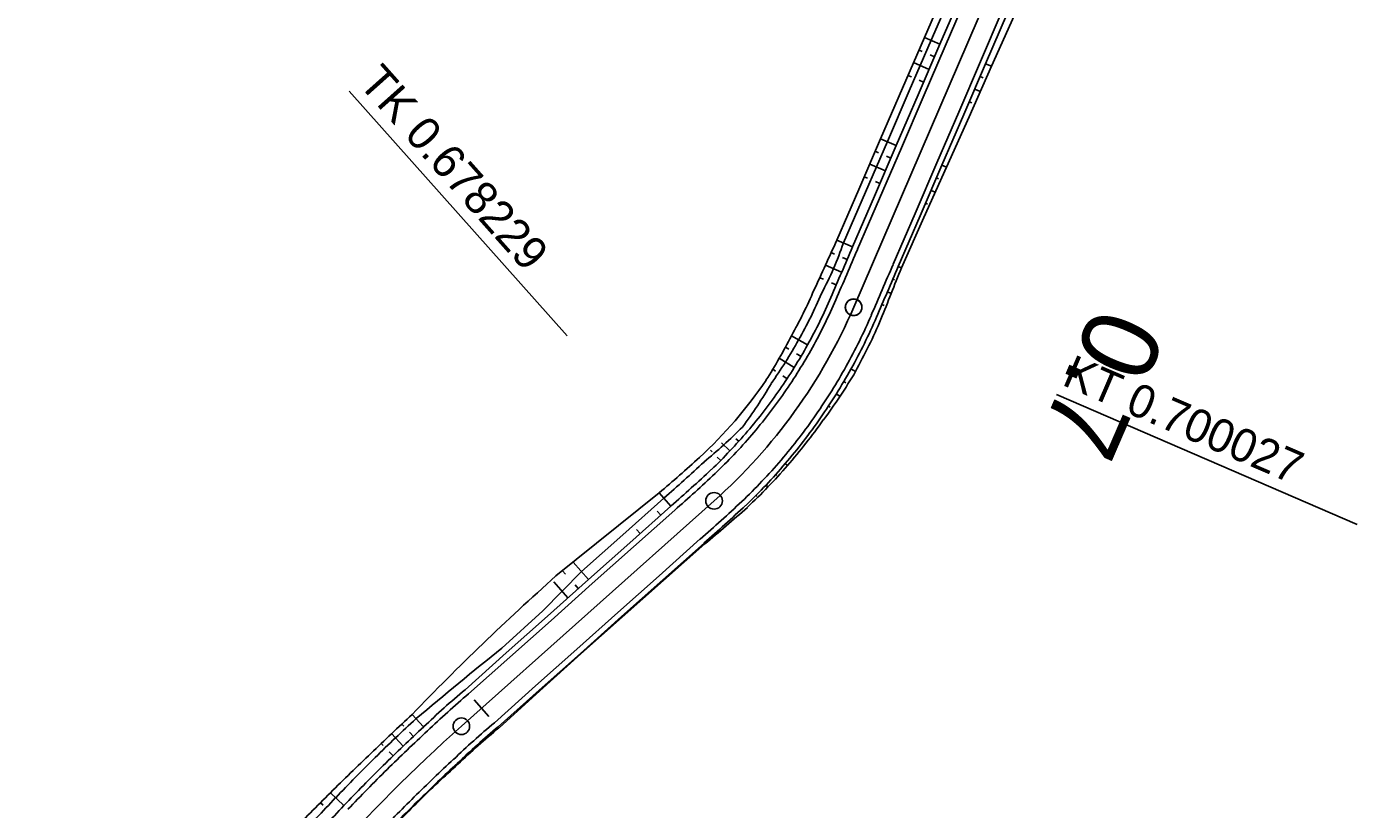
# Model space of a CAD drawing. Extents: x -481656 to -478728, y -1113199 to -1110710.
# Drawn here: x -480192.1 to -480071.5, y -1112507.2 to -1112436.3 of the extents above; entities that cross this region are included whole.
import ezdxf

# ---------------------------------------------------------------- set-up
doc = ezdxf.new("R2010")
doc.units = 0
for name, color, linetype in [('C14_HATCH_SLOPE_L', 7, 'Continuous'), ('C14_HATCH_SLOPE_R', 7, 'Continuous'), ('C14_HECTOMETRY', 7, 'Continuous'), ('C14_HLBODY', 7, 'Continuous'), ('C14_HRANA_TELESO', 7, 'Continuous'), ('C14_KORUNA', 7, 'Continuous'), ('C14_OSA', 7, 'Continuous'), ('C14_PRIKOP', 7, 'Continuous'), ('C14_STANICENI', 7, 'Continuous'), ('C14_VOZOVKA', 7, 'Continuous'), ('C14_ZPEVKRAJ', 7, 'Continuous')]:
    doc.layers.add(name, color=color, linetype=linetype)

msp = doc.modelspace()

# ---------------------------------------------------------------- linework, layer by layer
at = {"layer": 'C14_HATCH_SLOPE_L'}
for p, q in [((-480109.3, -1112437.88), (-480110.71, -1112437.27)), ((-480110.9, -1112438.55), (-480111.2, -1112438.42)), ((-480109.79, -1112439.02), (-480110.19, -1112438.85)), ((-480110.29, -1112440.17), (-480111.7, -1112439.56)), ((-480111.89, -1112440.84), (-480112.2, -1112440.71)), ((-480110.78, -1112441.32), (-480111.18, -1112441.15)), ((-480113.26, -1112447.06), (-480114.68, -1112446.45)), ((-480114.87, -1112447.72), (-480115.17, -1112447.59)), ((-480114.25, -1112449.35), (-480115.67, -1112448.74)), ((-480113.75, -1112448.21), (-480114.16, -1112448.03)), ((-480115.86, -1112450.02), (-480116.17, -1112449.89)), ((-480114.74, -1112450.5), (-480115.15, -1112450.32)), ((-480117.22, -1112456.24), (-480118.65, -1112455.63)), ((-480118.85, -1112456.9), (-480119.17, -1112456.76)), ((-480117.71, -1112457.39), (-480118.13, -1112457.21)), ((-480118.21, -1112458.54), (-480119.68, -1112457.9)), ((-480119.87, -1112459.18), (-480120.2, -1112459.04)), ((-480118.7, -1112459.69), (-480119.12, -1112459.51)), ((-480121.3, -1112465.11), (-480122.76, -1112464.3)), ((-480121.3, -1112465.11), (-480122.76, -1112464.3)), ((-480123, -1112465.5), (-480123.3, -1112465.32)), ((-480123, -1112465.5), (-480123.3, -1112465.32)), ((-480121.9, -1112466.15), (-480122.29, -1112465.92)), ((-480121.9, -1112466.15), (-480122.29, -1112465.92)), ((-480122.51, -1112467.17), (-480123.86, -1112466.33)), ((-480122.51, -1112467.17), (-480123.86, -1112466.33)), ((-480124.19, -1112467.5), (-480124.45, -1112467.33)), ((-480124.19, -1112467.5), (-480124.45, -1112467.33)), ((-480123.16, -1112468.18), (-480123.55, -1112467.92)), ((-480123.16, -1112468.18), (-480123.55, -1112467.92)), ((-480128.34, -1112474.72), (-480129.11, -1112473.99)), ((-480127.53, -1112473.84), (-480127.79, -1112473.61)), ((-480129.94, -1112474.81), (-480130.09, -1112474.66)), ((-480129.17, -1112475.58), (-480129.48, -1112475.27)), ((-480133.68, -1112479.71), (-480134.74, -1112478.51)), ((-480134.61, -1112480.54), (-480134.93, -1112480.18)), ((-480136.48, -1112482.2), (-480136.8, -1112481.84)), ((-480141.14, -1112486.36), (-480142.54, -1112484.79)), ((-480143.23, -1112485.89), (-480143.52, -1112485.57)), ((-480143.01, -1112488.02), (-480144.3, -1112486.58)), ((-480142.08, -1112487.19), (-480142.37, -1112486.86)), ((-480157.89, -1112499.64), (-480158.07, -1112499.45)), ((-480156.09, -1112499.71), (-480157.13, -1112498.58)), ((-480157.94, -1112501.45), (-480159.01, -1112500.32)), ((-480157.02, -1112500.57), (-480157.36, -1112500.2)), ((-480159.75, -1112501.4), (-480159.93, -1112501.21)), ((-480158.85, -1112502.32), (-480159.21, -1112501.96)), ((-480163.31, -1112506.83), (-480164.53, -1112505.68)), ((-480165.19, -1112506.81), (-480165.45, -1112506.58))]:
    msp.add_line(p, q, dxfattribs=at)
at = {"layer": 'C14_HATCH_SLOPE_R'}
for p, q in [((-480105.17, -1112439.66), (-480104.62, -1112439.89)), ((-480105.66, -1112440.8), (-480105.4, -1112440.92)), ((-480105.13, -1112441.03), (-480105.13, -1112441.03)), ((-480106.16, -1112441.95), (-480105.64, -1112442.17)), ((-480106.65, -1112443.1), (-480106.4, -1112443.21)), ((-480106.15, -1112443.31), (-480106.15, -1112443.31)), ((-480109.12, -1112448.84), (-480108.7, -1112449.02)), ((-480109.62, -1112449.99), (-480109.42, -1112450.07)), ((-480109.22, -1112450.16), (-480109.22, -1112450.16)), ((-480110.11, -1112451.14), (-480109.73, -1112451.3)), ((-480110.61, -1112452.28), (-480110.42, -1112452.36)), ((-480110.24, -1112452.44), (-480110.24, -1112452.44)), ((-480113.08, -1112458.02), (-480112.8, -1112458.15)), ((-480113.58, -1112459.17), (-480113.42, -1112459.24)), ((-480113.26, -1112459.31), (-480113.26, -1112459.31)), ((-480114.07, -1112460.32), (-480113.72, -1112460.47)), ((-480114.57, -1112461.47), (-480114.37, -1112461.55)), ((-480114.18, -1112461.63), (-480114.18, -1112461.63)), ((-480117.37, -1112467.3), (-480116.96, -1112467.53)), ((-480118.7, -1112469.55), (-480118.36, -1112469.76)), ((-480118.02, -1112468.44), (-480117.83, -1112468.54)), ((-480117.65, -1112468.66), (-480117.65, -1112468.66)), ((-480119.4, -1112470.65), (-480119.25, -1112470.75)), ((-480119.1, -1112470.85), (-480119.1, -1112470.85)), ((-480123.32, -1112475.87), (-480123.12, -1112476.04)), ((-480125.07, -1112477.81), (-480124.89, -1112477.98)), ((-480124.18, -1112476.85), (-480124.09, -1112476.94)), ((-480123.99, -1112477.02), (-480123.99, -1112477.02)), ((-480125.98, -1112478.75), (-480125.9, -1112478.83)), ((-480125.81, -1112478.91), (-480125.81, -1112478.91)), ((-480131.61, -1112483.9), (-480131.58, -1112483.93)), ((-480131.55, -1112483.97), (-480131.55, -1112483.97)), ((-480130.68, -1112483.07), (-480130.61, -1112483.14)), ((-480132.55, -1112484.73), (-480132.49, -1112484.79)), ((-480133.48, -1112485.56), (-480133.45, -1112485.59)), ((-480133.43, -1112485.62), (-480133.43, -1112485.62)), ((-480138.15, -1112489.72), (-480138.11, -1112489.77)), ((-480139.08, -1112490.55), (-480139.06, -1112490.57)), ((-480139.04, -1112490.59), (-480139.04, -1112490.59)), ((-480140.95, -1112492.22), (-480140.93, -1112492.23)), ((-480140.91, -1112492.25), (-480140.91, -1112492.25)), ((-480140.01, -1112491.38), (-480139.98, -1112491.42)), ((-480146.55, -1112497.21), (-480146.52, -1112497.24)), ((-480146.49, -1112497.27), (-480146.49, -1112497.27)), ((-480145.61, -1112496.37), (-480145.56, -1112496.43)), ((-480147.48, -1112498.04), (-480147.41, -1112498.11)), ((-480148.41, -1112498.87), (-480148.38, -1112498.91)), ((-480148.34, -1112498.95), (-480148.34, -1112498.95)), ((-480153.04, -1112503.02), (-480152.97, -1112503.08)), ((-480153.94, -1112503.86), (-480153.91, -1112503.89)), ((-480153.88, -1112503.92), (-480153.88, -1112503.92)), ((-480155.72, -1112505.55), (-480155.7, -1112505.58)), ((-480155.67, -1112505.6), (-480155.67, -1112505.6)), ((-480154.83, -1112504.7), (-480154.78, -1112504.76))]:
    msp.add_line(p, q, dxfattribs=at)
at = {"layer": 'C14_HECTOMETRY'}
msp.add_circle((-480117.13, -1112461.72), 0.75, dxfattribs=at)
at = {"layer": 'C14_HLBODY'}
for p, q in [((-480162.84, -1112442.14), (-480143.08, -1112464.31)), ((-480098.75, -1112469.61), (-480071.48, -1112481.37))]:
    msp.add_line(p, q, dxfattribs=at)
for centre in [(-480117.12, -1112461.7), (-480129.77, -1112479.24), (-480152.67, -1112499.65)]:
    msp.add_circle(centre, 0.75, dxfattribs=at)
at = {"layer": 'C14_HRANA_TELESO'}
for p, q in [((-480110.71, -1112437.27), (-480108.72, -1112432.68)), ((-480104.62, -1112439.89), (-480102.58, -1112435.33)), ((-480112.69, -1112441.86), (-480110.71, -1112437.27)), ((-480106.66, -1112444.46), (-480104.62, -1112439.89)), ((-480114.68, -1112446.45), (-480112.69, -1112441.86)), ((-480108.7, -1112449.02), (-480106.66, -1112444.46)), ((-480116.66, -1112451.04), (-480114.68, -1112446.45)), ((-480110.75, -1112453.58), (-480108.7, -1112449.02)), ((-480118.65, -1112455.63), (-480116.66, -1112451.04)), ((-480112.8, -1112458.15), (-480110.75, -1112453.58)), ((-480144.1, -1112486.04), (-480134.74, -1112478.51)), ((-480134.36, -1112486.45), (-480130.61, -1112483.14)), ((-480138.11, -1112489.77), (-480134.36, -1112486.45)), ((-480149, -1112492.58), (-480145.3, -1112489.21)), ((-480141.85, -1112493.08), (-480138.11, -1112489.77)), ((-480145.56, -1112496.43), (-480141.85, -1112493.08)), ((-480149.26, -1112499.79), (-480145.56, -1112496.43))]:
    msp.add_line(p, q, dxfattribs=at)
for centre, radius, start, end in [((-485943.29, -1109801.96), 6400.66, 335.461603, 335.50635), ((-473992.43, -1114890.71), 6586.07, 158.324428, 158.367956), ((-480163, -1112441.84), 46.08, 330.828, 336.5575), ((-480163.1, -1112442.04), 52.71, 331.0858, 336.8154), ((-480163.9, -1112443.35), 46.16, 327.2716, 333.005), ((-480158.18, -1112445.91), 39.98, 312.6689, 325.9265), ((-480162.22, -1112440.65), 52.65, 323.5666, 329.2985), ((-480162.71, -1112441.49), 52.54, 318.8842, 324.6141), ((-480224.17, -1112372.54), 138.66, 310.1615, 312.1723), ((-480162.75, -1112441.61), 52.5, 313.2855, 319.0153), ((-480231.26, -1112362.09), 157.43, 309.7394, 311.5913), ((-479986.79, -1112662.6), 236.47, 131.7, 136.0823), ((-480053.4, -1112612.14), 153.8, 132.4085, 134.3184), ((-480102.14, -1112556.62), 73.83, 129.667, 133.5171), ((-480055.36, -1112614.11), 153.87, 133.2838, 135.1942), ((-480053.64, -1112612.36), 147.68, 132.2735, 134.1835), ((-480057.21, -1112616.17), 154.03, 134.1648, 136.0763), ((-480052.61, -1112611.37), 147.69, 134.7368, 136.6466)]:
    msp.add_arc(centre, radius, start, end, dxfattribs=at)
at = {"layer": 'C14_KORUNA'}
for p, q in [((-480109.3, -1112437.88), (-480107.32, -1112433.28)), ((-480105.17, -1112439.66), (-480103.19, -1112435.06)), ((-480111.28, -1112442.47), (-480109.3, -1112437.88)), ((-480107.15, -1112444.25), (-480105.17, -1112439.66)), ((-480113.26, -1112447.06), (-480111.28, -1112442.47)), ((-480109.12, -1112448.84), (-480107.15, -1112444.25)), ((-480115.24, -1112451.65), (-480113.26, -1112447.06)), ((-480111.1, -1112453.43), (-480109.12, -1112448.84)), ((-480117.22, -1112456.24), (-480115.24, -1112451.65)), ((-480113.08, -1112458.02), (-480111.1, -1112453.43)), ((-480137.41, -1112483.03), (-480133.68, -1112479.71)), ((-480141.14, -1112486.36), (-480137.41, -1112483.03)), ((-480134.42, -1112486.39), (-480130.68, -1112483.07)), ((-480144.87, -1112489.69), (-480141.14, -1112486.36)), ((-480138.15, -1112489.72), (-480134.42, -1112486.39)), ((-480148.61, -1112493.01), (-480144.87, -1112489.69)), ((-480141.88, -1112493.05), (-480138.15, -1112489.72)), ((-480152.34, -1112496.34), (-480148.61, -1112493.01)), ((-480145.61, -1112496.37), (-480141.88, -1112493.05)), ((-480149.35, -1112499.7), (-480145.61, -1112496.37))]:
    msp.add_line(p, q, dxfattribs=at)
for centre, radius, start, end in [((-471553.39, -1116149.55), 9326.29, 156.670978, 156.701689), ((-520578.16, -1095022.28), 44061.64, 336.683075, 336.689578), ((-480163.03, -1112441.91), 47.75, 330.9256, 336.6551), ((-480163.03, -1112441.91), 52.25, 330.9256, 336.6551), ((-480163.03, -1112441.91), 47.75, 325.196, 330.9255), ((-480163.03, -1112441.91), 52.25, 325.196, 330.9256), ((-480163.03, -1112441.91), 47.75, 319.4664, 325.196), ((-480163.03, -1112441.91), 52.25, 319.4664, 325.196), ((-480163.03, -1112441.91), 47.75, 313.7368, 319.4664), ((-480227.79, -1112371.71), 143.25, 311.0724, 313.0404), ((-480163.03, -1112441.91), 52.25, 313.7368, 319.4664), ((-480233.83, -1112365.03), 156.75, 311.1489, 313.0057), ((-480103.35, -1112554.6), 76.12, 130.061, 133.8537), ((-480052.87, -1112611.63), 152.25, 132.6808, 134.5906), ((-480101.83, -1112556.27), 73.88, 130.0292, 133.8782), ((-480052.87, -1112611.63), 152.25, 134.5906, 136.5005), ((-480052.87, -1112611.63), 147.75, 132.6808, 134.5906), ((-480052.87, -1112611.63), 152.25, 136.5005, 138.4103), ((-480052.87, -1112611.63), 147.75, 134.5906, 136.5005)]:
    msp.add_arc(centre, radius, start, end, dxfattribs=at)
at = {"layer": 'C14_OSA'}
for p, q in [((-480117.12, -1112461.7), (-480076.44, -1112367.31)), ((-480152.67, -1112499.65), (-480129.77, -1112479.24))]:
    msp.add_line(p, q, dxfattribs=at)
for centre, radius, start, end in [((-480163.03, -1112441.91), 50, 311.7077, 336.6864), ((-480052.87, -1112611.63), 150, 131.7077, 158.1186)]:
    msp.add_arc(centre, radius, start, end, dxfattribs=at)
at = {"layer": 'C14_PRIKOP'}
for p, q in [((-480110.09, -1112437.53), (-480108.1, -1112432.95)), ((-480112.08, -1112442.12), (-480110.09, -1112437.53)), ((-480114.07, -1112446.71), (-480112.08, -1112442.12)), ((-480116.06, -1112451.29), (-480114.07, -1112446.71)), ((-480118.05, -1112455.88), (-480116.06, -1112451.29)), ((-480138.05, -1112482.31), (-480134.32, -1112478.99)), ((-480141.79, -1112485.63), (-480138.05, -1112482.31)), ((-480145.3, -1112489.21), (-480141.79, -1112485.63))]:
    msp.add_line(p, q, dxfattribs=at)
for centre, radius, start, end in [((-480146.02, -1112446.49), 29.5, 331.7223, 341.4402), ((-480162.99, -1112441.83), 46.83, 330.8136, 336.5432), ((-480162.99, -1112441.83), 46.82, 325.0838, 330.8134), ((-480164.95, -1112444.59), 46.98, 323.4712, 329.2149), ((-480160.56, -1112439.48), 46.97, 309.4939, 315.2392), ((-480226.32, -1112372.95), 140.39, 310.9473, 312.9416), ((-479873.28, -1112836.63), 440.9, 128.7078, 130.0156), ((-480053.08, -1112611.83), 153.27, 132.5743, 134.4842), ((-480053.07, -1112611.84), 153.28, 134.484, 136.3939), ((-480053.07, -1112611.84), 153.29, 136.3941, 138.3039)]:
    msp.add_arc(centre, radius, start, end, dxfattribs=at)
at = {"layer": 'C14_STANICENI'}
msp.add_line((-480150.18, -1112498.77), (-480151.51, -1112497.27), dxfattribs=at)
at = {"layer": 'C14_VOZOVKA'}
for p, q in [((-480108.84, -1112438.07), (-480106.86, -1112433.48)), ((-480105.63, -1112439.46), (-480103.65, -1112434.87)), ((-480110.82, -1112442.67), (-480108.84, -1112438.07)), ((-480107.6, -1112444.05), (-480105.63, -1112439.46)), ((-480112.8, -1112447.26), (-480110.82, -1112442.67)), ((-480109.58, -1112448.64), (-480107.6, -1112444.05)), ((-480114.78, -1112451.85), (-480112.8, -1112447.26)), ((-480111.56, -1112453.23), (-480109.58, -1112448.64)), ((-480116.76, -1112456.44), (-480114.78, -1112451.85)), ((-480113.54, -1112457.82), (-480111.56, -1112453.23)), ((-480137.08, -1112483.41), (-480133.34, -1112480.08)), ((-480134.75, -1112486.02), (-480131.02, -1112482.69)), ((-480140.81, -1112486.73), (-480137.08, -1112483.41)), ((-480138.48, -1112489.35), (-480134.75, -1112486.02)), ((-480144.54, -1112490.06), (-480140.81, -1112486.73)), ((-480148.27, -1112493.39), (-480144.54, -1112490.06)), ((-480142.21, -1112492.67), (-480138.48, -1112489.35)), ((-480152.01, -1112496.71), (-480148.27, -1112493.39)), ((-480145.95, -1112496), (-480142.21, -1112492.67)), ((-480149.68, -1112499.33), (-480145.95, -1112496))]:
    msp.add_line(p, q, dxfattribs=at)
for centre, radius, start, end in [((-481062.27, -1112051.69), 1028.5, 336.54709, 336.82558), ((-481852.02, -1111711.35), 1891.96, 336.6106, 336.76205), ((-480163.03, -1112441.91), 48.25, 330.9256, 336.6551), ((-480163.03, -1112441.91), 51.75, 330.9256, 336.6551), ((-480163.03, -1112441.91), 48.25, 325.196, 330.9255), ((-480163.03, -1112441.91), 51.75, 325.196, 330.9256), ((-480163.03, -1112441.91), 48.25, 319.4664, 325.196), ((-480163.03, -1112441.91), 51.75, 319.4664, 325.196), ((-480163.03, -1112441.91), 48.25, 313.7368, 319.4664), ((-480163.03, -1112441.91), 51.75, 313.7368, 319.4664), ((-480228.46, -1112370.97), 144.75, 311.0815, 313.0361), ((-480233.16, -1112365.78), 155.25, 311.141, 313.0091), ((-480103.18, -1112554.79), 75.88, 130.0576, 133.8563), ((-480102, -1112556.08), 74.12, 130.0329, 133.8754), ((-480052.87, -1112611.63), 151.75, 132.6808, 134.5906), ((-480052.87, -1112611.63), 148.25, 132.6808, 134.5906), ((-480052.87, -1112611.63), 151.75, 134.5906, 136.5005), ((-480052.87, -1112611.63), 148.25, 134.5906, 136.5005)]:
    msp.add_arc(centre, radius, start, end, dxfattribs=at)
at = {"layer": 'C14_ZPEVKRAJ'}
for p, q in [((-480108.84, -1112438.07), (-480106.86, -1112433.48)), ((-480105.63, -1112439.46), (-480103.65, -1112434.87)), ((-480110.82, -1112442.67), (-480108.84, -1112438.07)), ((-480107.6, -1112444.05), (-480105.63, -1112439.46)), ((-480112.8, -1112447.26), (-480110.82, -1112442.67)), ((-480109.58, -1112448.64), (-480107.6, -1112444.05)), ((-480114.78, -1112451.85), (-480112.8, -1112447.26)), ((-480111.56, -1112453.23), (-480109.58, -1112448.64)), ((-480116.76, -1112456.44), (-480114.78, -1112451.85)), ((-480113.54, -1112457.82), (-480111.56, -1112453.23)), ((-480137.08, -1112483.41), (-480133.34, -1112480.08)), ((-480134.75, -1112486.02), (-480131.02, -1112482.69)), ((-480140.81, -1112486.73), (-480137.08, -1112483.41)), ((-480138.48, -1112489.35), (-480134.75, -1112486.02)), ((-480144.54, -1112490.06), (-480140.81, -1112486.73)), ((-480148.27, -1112493.39), (-480144.54, -1112490.06)), ((-480142.21, -1112492.67), (-480138.48, -1112489.35)), ((-480152.01, -1112496.71), (-480148.27, -1112493.39)), ((-480145.95, -1112496), (-480142.21, -1112492.67)), ((-480149.68, -1112499.33), (-480145.95, -1112496))]:
    msp.add_line(p, q, dxfattribs=at)
for centre, radius, start, end in [((-481062.27, -1112051.69), 1028.5, 336.54709, 336.82558), ((-481852.02, -1111711.35), 1891.96, 336.6106, 336.76205), ((-480163.03, -1112441.91), 48.25, 330.9256, 336.6551), ((-480163.03, -1112441.91), 51.75, 330.9256, 336.6551), ((-480163.03, -1112441.91), 48.25, 325.196, 330.9255), ((-480163.03, -1112441.91), 51.75, 325.196, 330.9256), ((-480163.03, -1112441.91), 48.25, 319.4664, 325.196), ((-480163.03, -1112441.91), 51.75, 319.4664, 325.196), ((-480163.03, -1112441.91), 48.25, 313.7368, 319.4664), ((-480163.03, -1112441.91), 51.75, 313.7368, 319.4664), ((-480228.46, -1112370.97), 144.75, 311.0815, 313.0361), ((-480233.16, -1112365.78), 155.25, 311.141, 313.0091), ((-480103.18, -1112554.79), 75.88, 130.0576, 133.8563), ((-480102, -1112556.08), 74.12, 130.0329, 133.8754), ((-480052.87, -1112611.63), 151.75, 132.6808, 134.5906), ((-480052.87, -1112611.63), 148.25, 132.6808, 134.5906), ((-480052.87, -1112611.63), 151.75, 134.5906, 136.5005), ((-480052.87, -1112611.63), 148.25, 134.5906, 136.5005)]:
    msp.add_arc(centre, radius, start, end, dxfattribs=at)

# ---------------------------------------------------------------- texts
at = {"layer": 'C14_HECTOMETRY'}
msp.add_text('0.7', height=7, rotation=246.6095, dxfattribs=at).set_placement((-480095.17, -1112461.35))
at = {"layer": 'C14_HLBODY'}
for s, height, rotation, p in [('TK 0.678229', 2.999, 311.7077, (-480162.09, -1112441.47)), ('KT 0.700027', 3, 336.6864, (-480098.35, -1112468.7))]:
    msp.add_text(s, height=height, rotation=rotation, dxfattribs=at).set_placement(p)

doc.saveas('drawing.dxf')
